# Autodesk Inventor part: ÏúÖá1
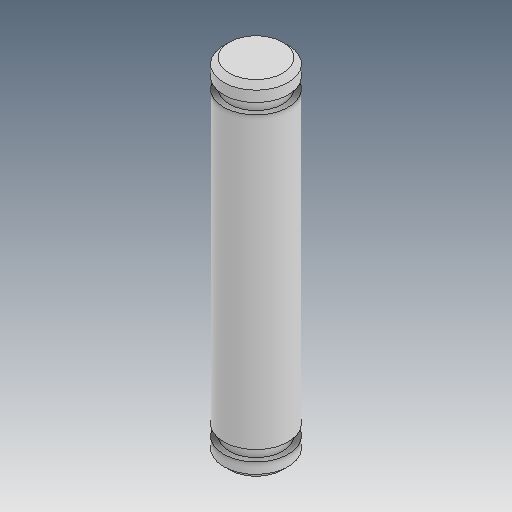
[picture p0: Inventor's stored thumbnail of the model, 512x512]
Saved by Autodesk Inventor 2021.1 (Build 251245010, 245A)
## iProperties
Created: 2014-12
Part Number: ÏúÖá1
Material: Ogólny
Document SubType Name: Modeling
Designer: user
Density: 1 g/cm^3
Appearance: Domyślna
Author: user
Revision Number: ÈÎºÎ
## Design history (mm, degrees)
feature "ÊäÈë1"
node "Bryła1"
